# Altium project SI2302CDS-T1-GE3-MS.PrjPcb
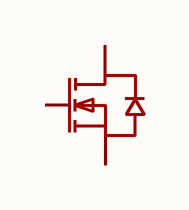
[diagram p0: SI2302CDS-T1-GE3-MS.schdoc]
1 sheet, 1 parts. Net scope: global (net labels, ports and power ports of the same name join across sheets).

## Sheet SI2302CDS-T1-GE3-MS.schdoc
size 127 x 101 mm

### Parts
Q?  si2302cds-t1-ge3-ms  [SOT-23-3_L2.9-W1.3-P1.90-LS2.4-BR]  (value not drawn)

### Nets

Not connected (* = marked no-connect by the designer): Q? 1(G) 2(S) 3(D)

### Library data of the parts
Q? = si2302cds-t1-ge3-ms: 数量:1个N沟道;漏源电压(Vdss):20V;连续漏极电流(Id):3A;导通电阻(RDS(on)):40mΩ@4.5V;耗散功率(Pd):1.56W;阈值电压(Vgs(th)):500mV;; Manufacturer: MSKSEMI(美森科); AddInBom: yes; ModelId: c62791f0466c4ae2a892c056b845b0ca; ModelName: SOT-23-3P_L2.9-W1.3-H1.0-LS2.4-P0.95; ModelTransform: 98.425,114.173,0,180,0,0,0.0005,-0.0005,0; Number: 1个N沟道; Drain to Source Voltage: 20V; Current - Continuous Drain(Id): 3A; Pd - Power Dissipation: 1.56W; Gate Threshold Voltage (Vgs(th)): 500mV; Gate Charge(Qg): 3.6nC@4.5V; Input Capacitance(Ciss): 180pF; Reverse Transfer Capacitance (Crss@Vds): 26pF; Type: N沟道; Output Capacitance(Coss): 32pF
